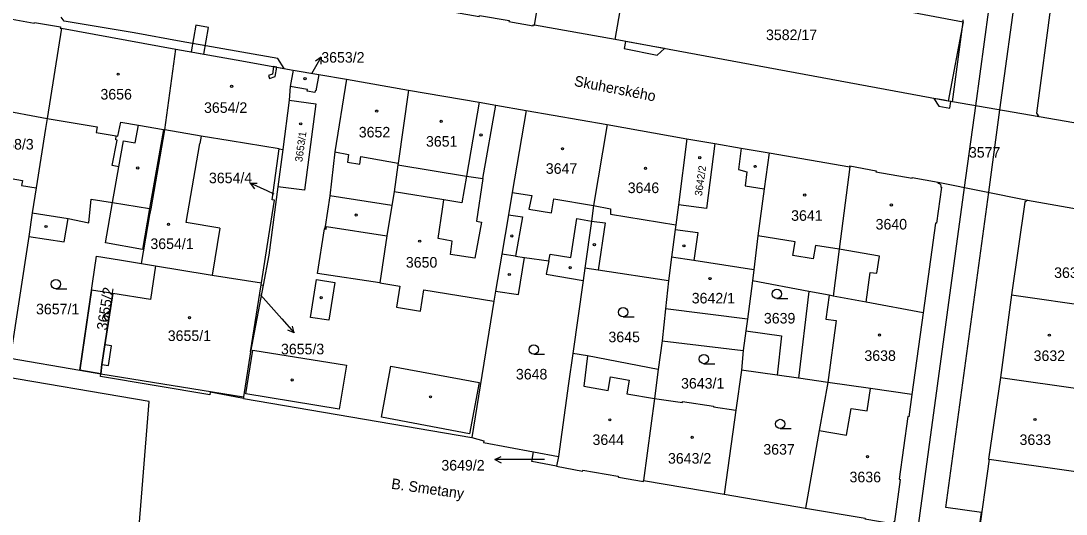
# Model space of a CAD drawing. Extents: x -756746 to -753363, y -1166406 to -1161727.
# Drawn here: x -755238.8 to -755070.8, y -1165629.2 to -1165549.9 of the extents above; entities that cross this region are included whole.
import ezdxf

# ---------------------------------------------------------------- set-up
doc = ezdxf.new("R2010")
doc.units = 0
for name, color, linetype in [('Hranice parcel', 7, 'Continuous'), ('Parcelní čísla', 7, 'Continuous'), ('Pop  PČ popisy', 7, 'Continuous'), ('Vnitřní kresba', 7, 'Continuous'), ('Věcná břemena k části', 7, 'Continuous'), ('Značky budov', 7, 'Continuous'), ('Značky kultur', 7, 'Continuous')]:
    doc.layers.add(name, color=color, linetype=linetype)

msp = doc.modelspace()

# ---------------------------------------------------------------- linework, layer by layer
at = {"layer": 'Hranice parcel'}
for p, q in [((-755143.26, -1165552.87), (-755140.98, -1165539.71)), ((-755232.27, -1165551.03), (-755234.6, -1165565.59)), ((-755232.27, -1165551.03), (-755213.93, -1165554.42)), ((-755143.26, -1165552.87), (-755156.27, -1165550.55)), ((-755215.7, -1165567.38), (-755213.93, -1165554.42)), ((-755195.05, -1165557.79), (-755195.55, -1165560.41)), ((-755195.05, -1165557.79), (-755190.93, -1165558.5)), ((-755190.93, -1165558.5), (-755186.45, -1165559.28)), ((-755186.45, -1165559.28), (-755176.48, -1165561)), ((-755176.48, -1165561), (-755165.12, -1165562.97)), ((-755075.13, -1165565.29), (-755089.06, -1165562.89)), ((-755243.99, -1165563.82), (-755234.6, -1165565.59)), ((-755157.58, -1165564.27), (-755144.56, -1165566.56)), ((-755144.56, -1165566.56), (-755131.76, -1165568.83)), ((-755217.9, -1165580.11), (-755215.7, -1165567.38)), ((-755131.76, -1165568.83), (-755133.12, -1165579.47)), ((-755131.76, -1165568.83), (-755127.24, -1165569.61)), ((-755197.29, -1165570.47), (-755196.73, -1165570.56)), ((-755118.52, -1165571.13), (-755105.55, -1165573.37)), ((-755091.37, -1165575.82), (-755091.39, -1165575.96)), ((-755091.37, -1165575.82), (-755076.99, -1165578.7)), ((-755076.99, -1165578.7), (-755058.63, -1165581.99)), ((-755237.57, -1165584.54), (-755240.56, -1165604.15)), ((-755219.42, -1165588.92), (-755217.16, -1165589.29)), ((-755148.16, -1165589.67), (-755148.44, -1165591.65)), ((-755200.19, -1165592.32), (-755200.14, -1165592)), ((-755148.44, -1165591.65), (-755150.1, -1165603.36)), ((-755112.17, -1165593.4), (-755121.21, -1165591.69)), ((-755201.89, -1165603.14), (-755200.19, -1165592.32)), ((-755199.87, -1165592.38), (-755201.89, -1165603.14)), ((-755200.19, -1165592.32), (-755199.87, -1165592.38)), ((-755162.51, -1165593.35), (-755162.78, -1165594.95)), ((-755112.17, -1165593.4), (-755113.79, -1165607.36)), ((-755162.78, -1165594.95), (-755166.32, -1165616.88)), ((-755079.58, -1165593.96), (-755081.35, -1165607.26)), ((-755093.79, -1165596.86), (-755095.61, -1165610)), ((-755135.74, -1165601.37), (-755136.35, -1165605.98)), ((-755135.74, -1165601.37), (-755122.69, -1165602.91)), ((-755122.69, -1165602.91), (-755122.99, -1165606.05)), ((-755240.56, -1165604.15), (-755229.34, -1165606.08)), ((-755225.82, -1165605.15), (-755225.96, -1165606.64)), ((-755225.96, -1165606.64), (-755229.34, -1165606.08)), ((-755136.35, -1165605.98), (-755136.96, -1165610.62)), ((-755122.99, -1165606.05), (-755123.89, -1165612.48)), ((-755109.11, -1165608.03), (-755113.79, -1165607.36)), ((-755203.06, -1165610.62), (-755203.28, -1165610.58)), ((-755203.06, -1165610.62), (-755166.32, -1165616.88)), ((-755136.96, -1165610.62), (-755138.7, -1165623.8)), ((-755156.41, -1165619.18), (-755152.38, -1165619.93)), ((-755152.38, -1165619.93), (-755152.69, -1165621.5)), ((-755083.16, -1165620.39), (-755085.89, -1165639.76)), ((-755138.7, -1165623.8), (-755125.77, -1165626)), ((-755125.77, -1165626), (-755112.66, -1165628.28))]:
    msp.add_line(p, q, dxfattribs=at)
for points in [[(-755156.27, -1165550.55), (-755154.03, -1165537.38), (-755153.01, -1165531.55)], [(-755169.09, -1165548.36), (-755169.11, -1165548.46), (-755165.12, -1165549.16), (-755165.09, -1165549.02), (-755160.33, -1165549.82), (-755160.36, -1165549.97), (-755156.46, -1165550.66), (-755156.44, -1165550.54), (-755156.27, -1165550.55)], [(-755075.13, -1165565.29), (-755075.47, -1165564.74), (-755073.16, -1165547.35), (-755072.91, -1165547.38), (-755072.97, -1165547.23)], [(-755240.24, -1165549.62), (-755236.68, -1165550.27), (-755236.65, -1165550.12), (-755232.45, -1165550.83), (-755232.49, -1165551.05), (-755232.27, -1165551.03)], [(-755089.06, -1165562.89), (-755087.35, -1165550.04), (-755087.31, -1165549.72)], [(-755089.06, -1165562.89), (-755089.72, -1165562.77), (-755143.26, -1165552.87)], [(-755213.93, -1165554.42), (-755203.3, -1165556.29), (-755198.92, -1165557.09), (-755195.05, -1165557.79)], [(-755190.93, -1165558.5), (-755191.39, -1165561.13), (-755191.5, -1165561.11), (-755191.55, -1165561.41), (-755192.81, -1165561.19), (-755192.76, -1165560.89), (-755195.55, -1165560.41)], [(-755186.45, -1165559.28), (-755188.34, -1165570.96), (-755189.16, -1165578.02)], [(-755195.55, -1165560.41), (-755195.69, -1165562.65), (-755196.73, -1165570.56)], [(-755176.48, -1165561), (-755178.16, -1165572.78), (-755178.2, -1165573.06), (-755178.79, -1165577.38)], [(-755165.12, -1165562.97), (-755167.2, -1165574.88), (-755167.95, -1165579.16), (-755170.82, -1165578.69), (-755178.79, -1165577.38)], [(-755165.12, -1165562.97), (-755162.48, -1165563.42), (-755157.58, -1165564.27)], [(-755157.58, -1165564.27), (-755159.82, -1165577.49), (-755160.43, -1165581.09), (-755161.5, -1165587.41), (-755162.51, -1165593.35)], [(-755234.6, -1165565.59), (-755234.86, -1165567.17), (-755236.39, -1165576.75)], [(-755144.56, -1165566.56), (-755146.74, -1165579.55), (-755147.09, -1165582.08), (-755148.16, -1165589.67)], [(-755062.22, -1165567.25), (-755062.34, -1165567.22), (-755062.4, -1165567.52), (-755075.13, -1165565.29)], [(-755197.29, -1165570.47), (-755205.2, -1165569.2), (-755209.83, -1165568.4), (-755215.7, -1165567.38)], [(-755127.24, -1165569.61), (-755128.6, -1165580.05), (-755133.12, -1165579.47)], [(-755127.24, -1165569.61), (-755123.04, -1165570.34), (-755118.52, -1165571.13)], [(-755245.19, -1165571.58), (-755240.28, -1165572.06), (-755240.41, -1165575.25), (-755238.59, -1165575.54), (-755238.72, -1165576.38), (-755236.39, -1165576.75)], [(-755200.14, -1165592), (-755198.94, -1165584.43), (-755198.04, -1165578.7), (-755198.45, -1165578.65), (-755197.29, -1165570.47)], [(-755196.73, -1165570.56), (-755197.52, -1165576.55), (-755198.97, -1165587.57), (-755199.87, -1165592.38)], [(-755118.52, -1165571.13), (-755119.32, -1165576.89), (-755120.36, -1165584.43), (-755121, -1165589.92), (-755121.21, -1165591.69)], [(-755105.55, -1165573.37), (-755107.27, -1165586.62), (-755108.24, -1165594.14)], [(-755105.55, -1165573.37), (-755105.54, -1165573.22), (-755101.33, -1165573.98), (-755101.35, -1165574.15), (-755095.55, -1165575.2), (-755095.53, -1165575.05), (-755091.37, -1165575.82)], [(-755236.39, -1165576.75), (-755237, -1165580.78), (-755237.57, -1165584.54)], [(-755090.94, -1165576.61), (-755090.8, -1165576.63), (-755091.62, -1165582.43), (-755091.76, -1165582.41), (-755093.79, -1165596.86)], [(-755091.39, -1165575.96), (-755091.18, -1165576.02), (-755091.16, -1165576.03), (-755090.99, -1165576.18), (-755090.92, -1165576.39), (-755090.94, -1165576.61)], [(-755237.57, -1165584.54), (-755231.88, -1165585.42), (-755231.21, -1165581.66), (-755227.92, -1165582.34), (-755227.5, -1165578.57), (-755224.09, -1165579.12), (-755218.12, -1165580.07), (-755217.9, -1165580.11)], [(-755189.16, -1165578.02), (-755189.92, -1165582.93), (-755189.99, -1165583.33), (-755189.75, -1165583.37), (-755189.69, -1165582.97), (-755179.97, -1165584.47), (-755181.14, -1165592.01), (-755177.91, -1165592.53), (-755178.46, -1165595.93), (-755174.6, -1165596.55), (-755174.05, -1165593.14), (-755162.78, -1165594.95)], [(-755178.79, -1165577.38), (-755179.21, -1165579.56), (-755189.16, -1165578.02)], [(-755219.42, -1165588.92), (-755218.07, -1165581.08), (-755217.9, -1165580.11)], [(-755133.12, -1165579.47), (-755133.53, -1165582.66), (-755133.63, -1165583.43), (-755134.2, -1165587.89), (-755134.69, -1165591.71)], [(-755076.99, -1165578.7), (-755077.42, -1165579.02), (-755079.58, -1165593.96)], [(-755229.34, -1165606.08), (-755226.69, -1165587.73), (-755222.96, -1165588.34), (-755219.42, -1165588.92)], [(-755162.51, -1165593.35), (-755158.81, -1165593.9), (-755157.87, -1165587.93), (-755153.95, -1165588.5), (-755154.35, -1165590.64), (-755148.44, -1165591.65)], [(-755217.16, -1165589.29), (-755218, -1165594.7), (-755224.05, -1165593.74), (-755225.33, -1165602), (-755225.82, -1165605.15)], [(-755217.16, -1165589.29), (-755208.74, -1165590.65), (-755208.05, -1165590.78), (-755200.14, -1165592)], [(-755134.69, -1165591.71), (-755145.99, -1165589.99), (-755148.16, -1165589.67)], [(-755134.69, -1165591.71), (-755135.17, -1165596.18), (-755135.74, -1165601.37)], [(-755121.21, -1165591.69), (-755122.03, -1165597.87), (-755122.27, -1165599.72), (-755122.69, -1165602.91)], [(-755108.24, -1165594.14), (-755108.85, -1165594.01), (-755112.17, -1165593.4)], [(-755093.79, -1165596.86), (-755102.91, -1165595.14), (-755108.24, -1165594.14)], [(-755079.58, -1165593.96), (-755066.13, -1165595.89), (-755063.78, -1165596.15), (-755061.15, -1165596.03)], [(-755220.11, -1165635.17), (-755218.22, -1165611.09), (-755244.01, -1165606.71), (-755270.43, -1165602.09), (-755270.99, -1165606.17), (-755284.61, -1165603.25), (-755297.52, -1165600.73), (-755307.95, -1165599.53), (-755319.09, -1165599.01)], [(-755201.89, -1165603.14), (-755203.02, -1165610.35), (-755203.06, -1165610.62)], [(-755150.1, -1165603.36), (-755150.77, -1165608.22), (-755152.38, -1165619.93)], [(-755136.35, -1165605.98), (-755147.75, -1165603.74), (-755150.1, -1165603.36)], [(-755203.28, -1165610.58), (-755208.38, -1165609.6), (-755208.46, -1165610.05), (-755226.04, -1165607.09), (-755225.96, -1165606.64)], [(-755113.79, -1165607.36), (-755117.22, -1165606.87), (-755122.99, -1165606.05)], [(-755109.11, -1165608.03), (-755110.49, -1165615.77), (-755112.66, -1165628.28)], [(-755095.61, -1165610), (-755102.21, -1165609.04), (-755109.11, -1165608.03)], [(-755081.35, -1165607.26), (-755083.28, -1165620.36), (-755083.16, -1165620.39)], [(-755081.35, -1165607.26), (-755068.13, -1165609.12), (-755063.49, -1165609.77)], [(-755095.61, -1165610), (-755096.09, -1165613.55), (-755096.24, -1165613.53), (-755097.6, -1165623.61), (-755097.45, -1165623.63), (-755098.36, -1165630.4), (-755098.76, -1165630.72)], [(-755136.96, -1165610.62), (-755132.46, -1165611.26), (-755132.44, -1165611.12), (-755127.45, -1165611.83), (-755127.47, -1165611.97), (-755123.89, -1165612.48)], [(-755123.89, -1165612.48), (-755125.72, -1165625.62), (-755125.77, -1165626)], [(-755166.32, -1165616.88), (-755164.41, -1165617.44), (-755164.47, -1165617.68), (-755156.41, -1165619.18)], [(-755152.69, -1165621.5), (-755156.7, -1165620.75), (-755156.41, -1165619.18)], [(-755083.16, -1165620.39), (-755069.96, -1165622.25), (-755068.91, -1165622.4)], [(-755152.69, -1165621.5), (-755148.53, -1165622.3), (-755148.5, -1165622.13), (-755142.83, -1165623.09), (-755142.73, -1165623.27), (-755138.73, -1165624), (-755138.7, -1165623.8)], [(-755112.66, -1165628.28), (-755103.1, -1165629.85), (-755103.12, -1165629.97), (-755098.76, -1165630.72)]]:
    msp.add_lwpolyline(points, dxfattribs=at)
at = {"layer": 'Pop  PČ popisy'}
for p, q in [((-755192.04, -1165558.34), (-755190.54, -1165555.74)), ((-755190.54, -1165555.74), (-755191.47, -1165556.36)), ((-755190.54, -1165555.74), (-755190.61, -1165556.86)), ((-755201.97, -1165576.01), (-755200.85, -1165575.96)), ((-755199.23, -1165577.23), (-755201.97, -1165576.01)), ((-755201.97, -1165576.01), (-755201.26, -1165576.87)), ((-755198.09, -1165577.75), (-755199.23, -1165577.23)), ((-755200.31, -1165593.96), (-755196.89, -1165597.82)), ((-755196.89, -1165597.82), (-755194.88, -1165600.05)), ((-755194.88, -1165600.05), (-755195.92, -1165599.64)), ((-755194.88, -1165600.05), (-755195.18, -1165598.97)), ((-755162.62, -1165620.45), (-755161.62, -1165619.95)), ((-755159.62, -1165620.45), (-755162.62, -1165620.45)), ((-755162.62, -1165620.45), (-755161.62, -1165620.95)), ((-755154.63, -1165620.41), (-755159.62, -1165620.45))]:
    msp.add_line(p, q, dxfattribs=at)
at = {"layer": 'Vnitřní kresba'}
for p, q in [((-755098.18, -1165548), (-755087.35, -1165550.04)), ((-755087.35, -1165550.04), (-755089.72, -1165562.77)), ((-755195.69, -1165562.65), (-755191.38, -1165563.22)), ((-755191.38, -1165563.22), (-755193.22, -1165577.11)), ((-755164.56, -1165575.24), (-755162.48, -1165563.42)), ((-755234.6, -1165565.59), (-755226.55, -1165566.93)), ((-755223.26, -1165568.42), (-755222.78, -1165566.16)), ((-755222.78, -1165566.16), (-755219.92, -1165566.65)), ((-755220.43, -1165569.52), (-755219.92, -1165566.65)), ((-755219.92, -1165566.65), (-755215.89, -1165567.35)), ((-755226.55, -1165566.93), (-755226.7, -1165567.84)), ((-755226.7, -1165567.84), (-755223.51, -1165568.38)), ((-755223.57, -1165569.03), (-755223.51, -1165568.38)), ((-755223.51, -1165568.38), (-755223.26, -1165568.42)), ((-755215.89, -1165567.35), (-755218.12, -1165580.07)), ((-755215.89, -1165567.35), (-755215.7, -1165567.38)), ((-755209.83, -1165568.4), (-755210.03, -1165569.6)), ((-755224.13, -1165573.15), (-755223.33, -1165569.08)), ((-755223.33, -1165569.08), (-755223.57, -1165569.03)), ((-755223.05, -1165573.34), (-755222.31, -1165569.18)), ((-755222.31, -1165569.18), (-755220.43, -1165569.52)), ((-755188.34, -1165570.96), (-755186.13, -1165571.37)), ((-755186.13, -1165571.37), (-755186.31, -1165572.58)), ((-755184.34, -1165572.95), (-755184.18, -1165571.71)), ((-755184.18, -1165571.71), (-755178.16, -1165572.78)), ((-755123.04, -1165570.34), (-755123.47, -1165573.78)), ((-755223.05, -1165573.34), (-755224.13, -1165573.15)), ((-755224.09, -1165579.12), (-755223.05, -1165573.34)), ((-755186.31, -1165572.58), (-755184.34, -1165572.95)), ((-755178.2, -1165573.06), (-755167.2, -1165574.88)), ((-755167.2, -1165574.88), (-755164.56, -1165575.24)), ((-755164.56, -1165575.24), (-755165.58, -1165582.11)), ((-755123.47, -1165573.78), (-755122.11, -1165574.17)), ((-755122.11, -1165574.17), (-755122.4, -1165576.43)), ((-755193.22, -1165577.11), (-755197.52, -1165576.55)), ((-755122.4, -1165576.43), (-755119.32, -1165576.89)), ((-755159.82, -1165577.49), (-755156.7, -1165577.98)), ((-755156.7, -1165577.98), (-755157.14, -1165580.18)), ((-755153.51, -1165580.76), (-755153.16, -1165578.51)), ((-755153.16, -1165578.51), (-755146.74, -1165579.55)), ((-755225.24, -1165585.58), (-755224.09, -1165579.12)), ((-755218.12, -1165580.07), (-755219.27, -1165586.66)), ((-755179.21, -1165579.56), (-755179.97, -1165584.47)), ((-755171.75, -1165584.9), (-755171.04, -1165580.17)), ((-755171.04, -1165580.17), (-755170.82, -1165578.69)), ((-755157.14, -1165580.18), (-755153.51, -1165580.76)), ((-755146.74, -1165579.55), (-755144.04, -1165580.13)), ((-755144.04, -1165580.13), (-755144.05, -1165580.95)), ((-755237, -1165580.78), (-755231.21, -1165581.66)), ((-755160.43, -1165581.09), (-755158.16, -1165581.38)), ((-755158.16, -1165581.38), (-755159.29, -1165587.73)), ((-755150.39, -1165587.92), (-755149.45, -1165581.66)), ((-755149.45, -1165581.66), (-755147.09, -1165582.08)), ((-755144.05, -1165580.95), (-755133.53, -1165582.66)), ((-755206.85, -1165583.22), (-755208.05, -1165590.78)), ((-755191.12, -1165590.53), (-755189.99, -1165583.33)), ((-755164.77, -1165582.24), (-755165.82, -1165588.06)), ((-755165.58, -1165582.11), (-755164.77, -1165582.24)), ((-755147.09, -1165582.08), (-755144.91, -1165582.38)), ((-755144.91, -1165582.38), (-755145.99, -1165589.99)), ((-755169.47, -1165585.31), (-755171.75, -1165584.9)), ((-755169.74, -1165587.44), (-755169.47, -1165585.31)), ((-755114.34, -1165585.44), (-755120.36, -1165584.43)), ((-755219.27, -1165586.66), (-755225.24, -1165585.58)), ((-755114.71, -1165587.6), (-755114.34, -1165585.44)), ((-755111.08, -1165586.01), (-755111.45, -1165588.16)), ((-755107.27, -1165586.62), (-755111.08, -1165586.01)), ((-755100.8, -1165587.7), (-755107.27, -1165586.62)), ((-755165.82, -1165588.06), (-755169.74, -1165587.44)), ((-755159.29, -1165587.73), (-755161.5, -1165587.41)), ((-755159.29, -1165587.73), (-755157.87, -1165587.93)), ((-755153.95, -1165588.5), (-755153.74, -1165587.41)), ((-755153.74, -1165587.41), (-755150.39, -1165587.92)), ((-755130.63, -1165588.44), (-755134.2, -1165587.89)), ((-755121, -1165589.92), (-755130.63, -1165588.44)), ((-755111.45, -1165588.16), (-755114.71, -1165587.6)), ((-755101.21, -1165590.46), (-755100.8, -1165587.7)), ((-755102.91, -1165595.14), (-755102.29, -1165590.35)), ((-755102.29, -1165590.35), (-755101.21, -1165590.46)), ((-755192.27, -1165597.57), (-755191.3, -1165591.49)), ((-755191.3, -1165591.49), (-755188.34, -1165591.96)), ((-755181.14, -1165592.01), (-755191.12, -1165590.53)), ((-755188.34, -1165591.96), (-755189.3, -1165598.04)), ((-755108.85, -1165594.01), (-755109.39, -1165597.85)), ((-755122.03, -1165597.87), (-755135.17, -1165596.18)), ((-755189.3, -1165598.04), (-755192.27, -1165597.57)), ((-755109.39, -1165597.85), (-755107.77, -1165598.07)), ((-755107.77, -1165598.07), (-755109.11, -1165608.03)), ((-755122.27, -1165599.72), (-755116.52, -1165600.54)), ((-755116.52, -1165600.54), (-755117.22, -1165606.87)), ((-755202.65, -1165609.89), (-755201.52, -1165602.84)), ((-755201.52, -1165602.84), (-755186.47, -1165605.27)), ((-755147.75, -1165603.74), (-755148.31, -1165608.65)), ((-755186.47, -1165605.27), (-755187.66, -1165612.36)), ((-755180.87, -1165613.63), (-755179.35, -1165605.4)), ((-755179.35, -1165605.4), (-755165.12, -1165608.05)), ((-755225.96, -1165606.64), (-755203.02, -1165610.35)), ((-755144.39, -1165609.33), (-755144.01, -1165607.14)), ((-755144.01, -1165607.14), (-755141.02, -1165607.66)), ((-755165.12, -1165608.05), (-755166.72, -1165616.29)), ((-755148.31, -1165608.65), (-755144.39, -1165609.33)), ((-755141.02, -1165607.66), (-755141.4, -1165609.85)), ((-755187.66, -1165612.36), (-755202.65, -1165609.89)), ((-755141.4, -1165609.85), (-755136.96, -1165610.62)), ((-755102.77, -1165612.62), (-755102.21, -1165609.04)), ((-755166.72, -1165616.29), (-755180.87, -1165613.63)), ((-755106.1, -1165616.53), (-755105.32, -1165612.23)), ((-755105.32, -1165612.23), (-755102.77, -1165612.62)), ((-755110.49, -1165615.77), (-755106.1, -1165616.53))]:
    msp.add_line(p, q, dxfattribs=at)
for points in [[(-755206.85, -1165583.22), (-755212.27, -1165582.29), (-755210.03, -1165569.6)], [(-755133.63, -1165583.43), (-755130.01, -1165583.93), (-755130.63, -1165588.44)], [(-755225.82, -1165605.15), (-755224.74, -1165605.33), (-755224.24, -1165602.17), (-755225.33, -1165602)]]:
    msp.add_lwpolyline(points, dxfattribs=at)
at = {"layer": 'Věcná břemena k části'}
for points in [[(-755084.79, -1165631.93), (-755084.37, -1165628.96), (-755090.13, -1165628.18), (-755083.23, -1165577.45), (-755081.42, -1165564.21), (-755075.78, -1165522.75), (-755073.43, -1165488.08), (-755073.11, -1165483.44), (-755119.79, -1165475.23), (-755118.72, -1165469.33), (-755221.56, -1165450.71), (-755228.32, -1165449.49), (-755213.31, -1165370.15)], [(-755217.98, -1165373.33), (-755233, -1165452.71), (-755222.33, -1165454.64), (-755124.86, -1165472.28), (-755126.08, -1165479.02), (-755123.12, -1165479.56), (-755122.98, -1165478.74), (-755077.34, -1165486.76), (-755077.39, -1165487.41), (-755079.76, -1165522.33), (-755085.37, -1165563.53), (-755087.15, -1165576.67), (-755094.28, -1165629.06), (-755107.71, -1165727.86)], [(-755240.24, -1165549.62), (-755236.68, -1165550.27), (-755236.65, -1165550.12), (-755232.45, -1165550.83), (-755232.49, -1165551.05), (-755232.27, -1165551.03), (-755213.93, -1165554.42), (-755203.3, -1165556.29), (-755198.92, -1165557.09), (-755198.19, -1165557.22), (-755197.69, -1165557.31), (-755196.48, -1165557.53), (-755197.5, -1165555.95), (-755213.05, -1165553.19), (-755220.6, -1165551.78), (-755231.88, -1165549.91), (-755232.34, -1165549.28)]]:
    msp.add_lwpolyline(points, dxfattribs=at)
for points in [[(-755211.45, -1165554.86), (-755209.4, -1165555.22), (-755208.66, -1165550.95), (-755210.7, -1165550.59)], [(-755135.36, -1165554.33), (-755136.28, -1165554.16), (-755136.89, -1165554.05), (-755141.61, -1165553.17), (-755141.85, -1165554.33), (-755136.51, -1165555.4)], [(-755197.69, -1165557.31), (-755198.19, -1165557.22), (-755198.37, -1165558.43), (-755199.02, -1165558.66), (-755198.86, -1165559.13), (-755197.93, -1165558.81)], [(-755092.03, -1165562.34), (-755091.26, -1165563.59), (-755089.5, -1165563.93), (-755089.29, -1165562.85), (-755089.72, -1165562.77), (-755090.37, -1165562.65), (-755091.03, -1165562.53)], [(-755225.96, -1165606.64), (-755225.82, -1165605.15), (-755225.33, -1165602), (-755225.06, -1165600.28), (-755224.94, -1165599.5), (-755224.05, -1165593.74), (-755227.48, -1165593.19), (-755229.34, -1165606.08)], [(-755225.96, -1165606.64), (-755225.82, -1165605.15), (-755225.33, -1165602), (-755224.05, -1165593.74), (-755227.48, -1165593.19), (-755229.34, -1165606.08)], [(-755225.62, -1165597.32), (-755225.04, -1165598.14), (-755224.69, -1165597.89), (-755224.48, -1165596.52)]]:
    msp.add_lwpolyline(points, close=True, dxfattribs=at)
at = {"layer": 'Značky budov'}
for centre in [(-755223.18, -1165558.46), (-755193.14, -1165559.17), (-755204.95, -1165560.41), (-755181.62, -1165564.39), (-755193.83, -1165566.44), (-755171.26, -1165566.03), (-755164.85, -1165568.23), (-755151.74, -1165570.45), (-755129.68, -1165571.88), (-755220.04, -1165573.53), (-755138.41, -1165573.6), (-755120.77, -1165573.29), (-755112.81, -1165577.9), (-755098.88, -1165579.49), (-755184.92, -1165581.11), (-755234.78, -1165582.95), (-755215.1, -1165582.61), (-755174.71, -1165585.32), (-755159.9, -1165584.48), (-755146.62, -1165585.88), (-755132.23, -1165586.06), (-755150.52, -1165589.57), (-755160.3, -1165590.67), (-755128.03, -1165591.33), (-755190.54, -1165594.41), (-755211.71, -1165597.61), (-755100.78, -1165600.42), (-755073.47, -1165600.44), (-755195.21, -1165607.64), (-755172.96, -1165610.35), (-755144.13, -1165614.06), (-755075.79, -1165613.99), (-755130.9, -1165616.86), (-755102.72, -1165619.97)]:
    msp.add_circle(centre, 0.175, dxfattribs=at)
at = {"layer": 'Značky kultur'}
for p, q in [((-755233.19, -1165592.97), (-755231.44, -1165592.97)), ((-755117.27, -1165594.54), (-755115.52, -1165594.54)), ((-755142, -1165597.5), (-755140.25, -1165597.5)), ((-755156.37, -1165603.51), (-755154.62, -1165603.51)), ((-755129.01, -1165605.02), (-755127.26, -1165605.02)), ((-755116.74, -1165615.47), (-755114.99, -1165615.47))]:
    msp.add_line(p, q, dxfattribs=at)
for centre in [(-755233.19, -1165592.22), (-755117.27, -1165593.79), (-755142, -1165596.75), (-755156.37, -1165602.76), (-755129.01, -1165604.27), (-755116.74, -1165614.72)]:
    msp.add_circle(centre, 0.75, dxfattribs=at)

# ---------------------------------------------------------------- texts
at = {"layer": 'Parcelní čísla'}
for s, p in [('3582/17', (-755119.03, -1165552.97)), ('3653/2', (-755190.53, -1165556.6)), ('3656', (-755226.03, -1165562.53)), ('3654/2', (-755209.38, -1165564.68)), ('3652', (-755184.5, -1165568.63)), ('3651', (-755173.7, -1165570.11)), ('3658/3', (-755243.72, -1165570.57)), ('3577', (-755086.41, -1165571.88)), ('3647', (-755154.43, -1165574.48)), ('3654/4', (-755208.59, -1165575.99)), ('3646', (-755141.26, -1165577.58)), ('3641', (-755114.99, -1165582.04)), ('3640', (-755101.41, -1165583.44)), ('3654/1', (-755218, -1165586.58)), ('3650', (-755176.93, -1165589.57)), ('3631', (-755072.71, -1165591.23)), ('3642/1', (-755130.97, -1165595.33)), ('3657/1', (-755236.39, -1165597.08)), ('3639', (-755119.37, -1165598.56)), ('3655/1', (-755215.21, -1165601.37)), ('3645', (-755144.36, -1165601.57)), ('3655/3', (-755197.01, -1165603.52)), ('3638', (-755103.21, -1165604.57)), ('3632', (-755076.01, -1165604.59)), ('3648', (-755159.24, -1165607.56)), ('3643/1', (-755132.69, -1165609.03)), ('3644', (-755146.92, -1165618.1)), ('3633', (-755078.27, -1165618.1)), ('3637', (-755119.46, -1165619.65)), ('3649/2', (-755171.22, -1165622.21)), ('3643/2', (-755134.79, -1165621.1)), ('3636', (-755105.6, -1165624.1))]:
    msp.add_text(s, height=1.7, dxfattribs=at).set_placement(p)
for s, height, rotation, p in [('3653/1', 1.2, 82, (-755193.59, -1165572.62)), ('3642/2', 1.2, 82, (-755129.33, -1165578.1)), ('3655/2', 1.7, 81, (-755224.99, -1165599.74))]:
    msp.add_text(s, height=height, rotation=rotation, dxfattribs=at).set_placement(p)
at = {"layer": 'Pop  PČ popisy'}
for s, rotation, p in [('Skuherského', 349, (-755149.97, -1165560.32)), ('B. Smetany', 352, (-755179.35, -1165625.13))]:
    msp.add_text(s, height=1.7, rotation=rotation, dxfattribs=at).set_placement(p)

doc.saveas('drawing.dxf')
